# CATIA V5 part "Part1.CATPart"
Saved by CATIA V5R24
Part number: Link1-2
Bounding box of the stored display mesh (mm): x 0 to 20, y -105 to 105, z 0 to 110
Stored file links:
  G:\_CAD수업\DMU_paradoxes\4bar_move\Part1.CATPart
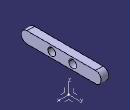
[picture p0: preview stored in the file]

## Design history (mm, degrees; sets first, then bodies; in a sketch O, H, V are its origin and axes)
AxisSystem1: origin (0, 0, 0), X (1, 0, 0), Y (0, 1, 0), Z (0, 0, 1)
Body1 (main body)
  Sketch1 on YZ plane of AxisSystem1, origin (0, 0, 0), H (0, 1, 0), V (0, 0, 1)
    line L1 (-105, 110) -> (105, 110)
    line L2 (105, 110) -> (105, 80)
    line L3 (105, 80) -> (-105, 80)
    line L4 (-105, 80) -> (-105, 110)
    circle A1 centre (30, 95) radius 10
    circle A2 centre (-25, 95) radius 10
    length L2 = 30
    length L1 = 210
    horizontal: L1 H, L3 H
    vertical: L2 V, L4 V
  Pad1: profile Sketch1, direction (1, 0, 0), length 20
  TritangentFillet1: Face1 face of Pad1 from Sketch1.L1, Face2 face of Pad1 from Sketch1.L3, RemoveFace face of Pad1 from Sketch1.L4
  TritangentFillet2: Face1 face of Pad1 from Sketch1.L1, Face2 face of Pad1 from Sketch1.L3, RemoveFace face of Pad1 from Sketch1.L2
